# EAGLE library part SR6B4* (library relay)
Safety Relay SR6 SCHRACK sensitive 6 pole 8 A Source: http://www.schrack.com/.. 6688.pdf
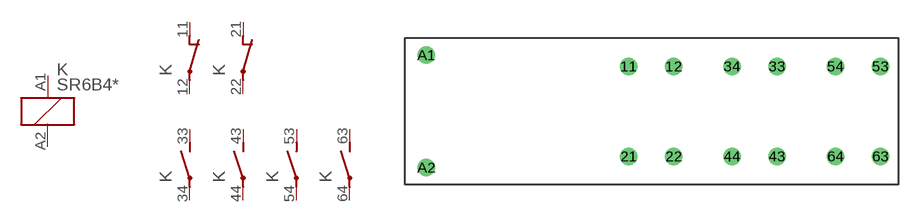
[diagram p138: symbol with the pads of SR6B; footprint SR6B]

Designator prefix K; gates 1=K 2=O 3=O 4=S 5=S 6=S 7=S

## SR6B4S05 (OC_FARNELL: unknown; OC_NEWARK: unknown), SR6B4S06 (OC_FARNELL: unknown; OC_NEWARK: unknown), SR6B4S09 (OC_FARNELL: unknown; OC_NEWARK: unknown), SR6B4S12 (OC_FARNELL: unknown; OC_NEWARK: unknown), SR6B4S15 (OC_FARNELL: unknown; OC_NEWARK: unknown), SR6B4S18 (OC_FARNELL: unknown; OC_NEWARK: unknown), SR6B4S21 (OC_FARNELL: unknown; OC_NEWARK: unknown), SR6B4S24 (OC_FARNELL: unknown; OC_NEWARK: unknown), SR6B4S36 (OC_FARNELL: unknown; OC_NEWARK: unknown), SR6B4S40 (OC_FARNELL: unknown; OC_NEWARK: unknown), SR6B4S48 (OC_FARNELL: unknown; OC_NEWARK: unknown)  [SR6B]
11  2:O  pas
12  2:P  pas
21  3:O  pas
22  3:P  pas
33  4:S  pas
34  4:P  pas
43  5:S  pas
44  5:P  pas
53  6:S  pas
54  6:P  pas
63  7:S  pas
64  7:P  pas
A1  1:1  pas
A2  1:2  pas

## Footprint SR6B (pad centres in mm)
Safety Relay SR6 SCHRACK sensitive 6 pole 8 A, Type A Source: http://www.schrack.com/.. 6688.pdf
drill 1.3 pad 1 round: 11 -0.3,4.7; 12 4.7,4.7; 21 -0.3,-5.3; 22 4.7,-5.3; 33 16.2,4.7; 34 11.2,4.7; 43 16.2,-5.3; 44 11.2,-5.3; 53 27.7,4.7; 54 22.7,4.7; 63 27.7,-5.3; 64 22.7,-5.3; A1 -22.8,5.95; A2 -22.8,-6.55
